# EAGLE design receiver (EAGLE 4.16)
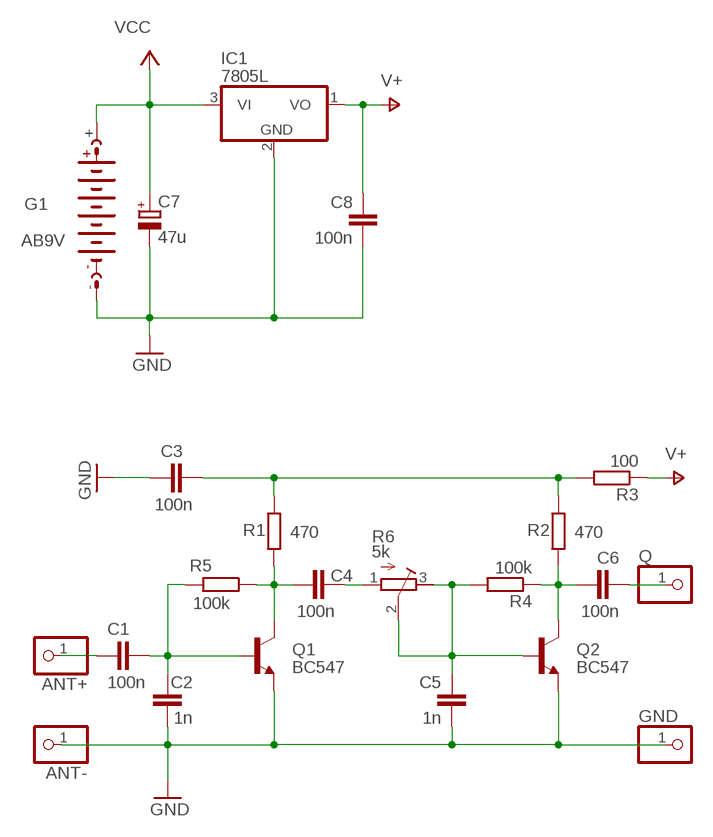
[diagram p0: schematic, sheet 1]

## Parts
ANT+  PINHD-1X1  [1X01]
ANT-  PINHD-1X1  [1X01]
C1  100n  C-EU050-035X075  [C050-035X075]
C2  1n  C-EU050-035X075  [C050-035X075]
C3  100n  C-EU050-035X075  [C050-035X075]
C4  100n  C-EU050-035X075  [C050-035X075]
C5  1n  C-EU050-035X075  [C050-035X075]
C6  100n  C-EU050-035X075  [C050-035X075]
C7  47u  CPOL-EUE5-10.5  [E5-10,5]
C8  100n  C-EU050-035X075  [C050-035X075]
G1  AB9V  [AB9V]
GND  PINHD-1X1  [1X01]
IC1  7805L  [TO92]
Q  PINHD-1X1  [1X01]
Q1  BC547  [TO92]
Q2  BC547  [TO92]
R1  470  R-EU_0411/3V  [0411V]
R2  470  R-EU_0411/3V  [0411V]
R3  100  R-EU_0411/3V  [0411V]
R4  100k  R-EU_0411/3V  [0411V]
R5  100k  R-EU_0411/3V  [0411V]
R6  5k  R-TRIMM3339P  [RTRIM3339P]

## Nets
GND: ANT-.1 C2.1 C3.1 C5.1 C7.- C8.1 G1.- GND.1 IC1.2(GND) Q1.1(E) Q2.1(E)
N$1: C1.1 C2.2 Q1.2(B) R5.2
N$2: C4.2 R6.1(E)
N$3: C4.1 Q1.3(C) R1.1 R5.1
N$4: ANT+.1 C1.2
N$5: C6.1 Q2.3(C) R2.1 R4.1
N$6: C3.2 R1.2 R2.2 R3.2
N$7: C6.2 Q.1
N$12: C5.2 Q2.2(B) R4.2 R6.2(S) R6.3(A)
V+: C8.2 IC1.1(VO) R3.1
VCC: C7.+ G1.+ IC1.3(VI)

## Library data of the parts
ANT+ ANT- GND Q = pinhead:PINHD-1X1: PIN HEADER
C1-C6 C8 = rcl:C-EU: CAPACITOR, European symbol
C7 = rcl:CPOL-EU: POLARIZED CAPACITOR, European symbol
G1 = battery:AB9V: 9-V BATTERY CLIP
IC1 = linear:78*: Positive VOLTAGE REGULATOR Source: http://cache.national.com/ds/LM/LM78L05.pdf http://www.fairchildsemi.com/ds/LM/LM7805.pdf
Q1 Q2 = transistor-npn:BC547*: NPN Transistor
R1-R5 = rcl:R-EU_: RESISTOR, European symbol
R6 = rcl:R-TRIMM: Trimm resistor

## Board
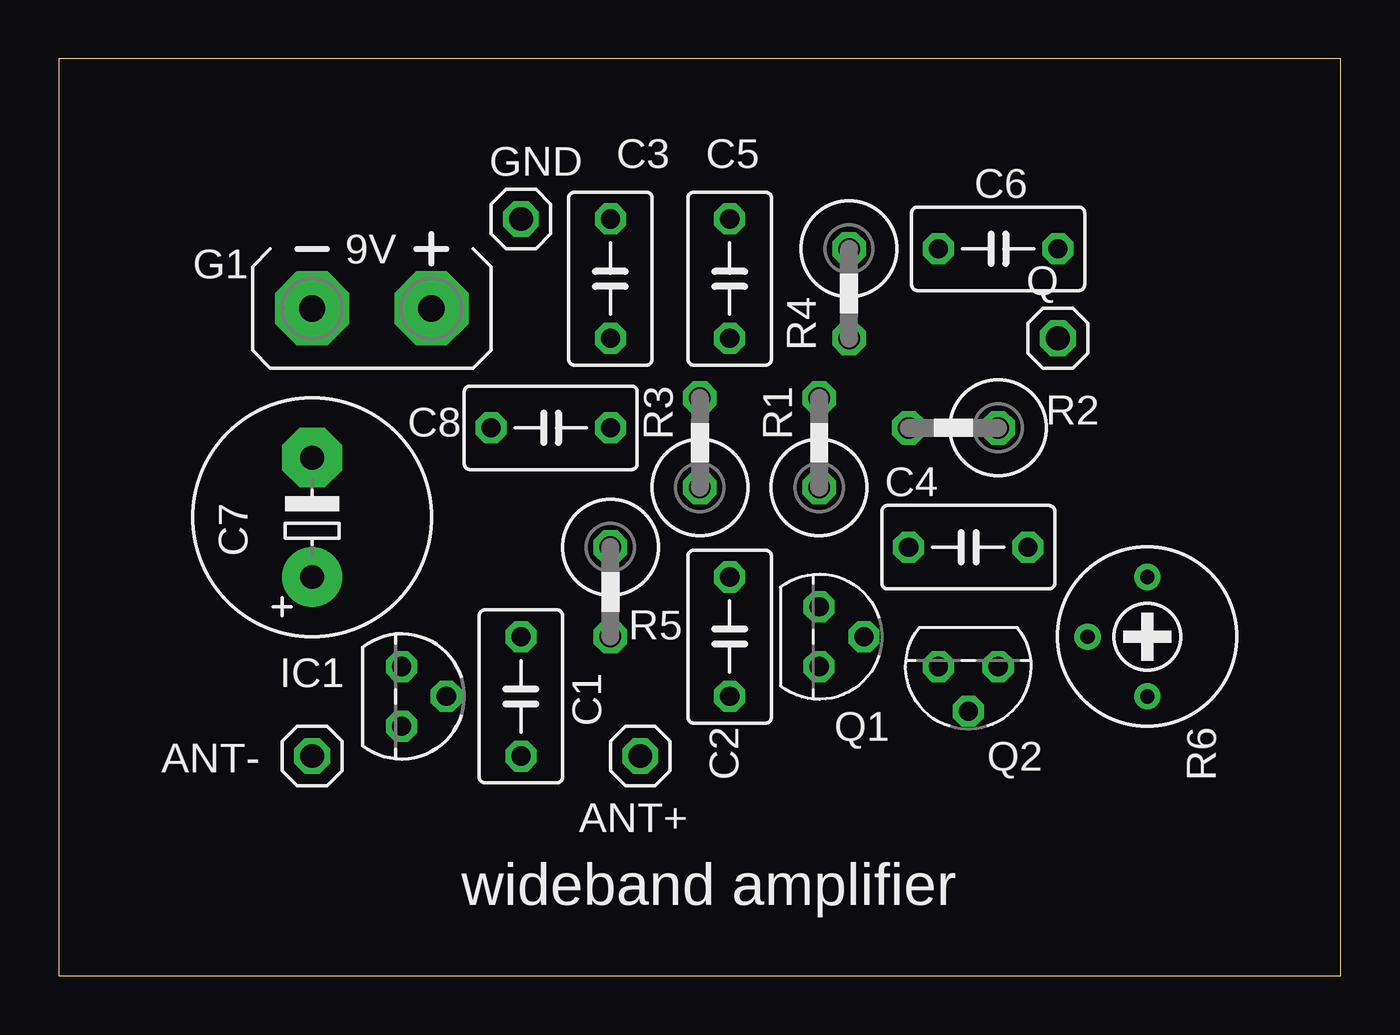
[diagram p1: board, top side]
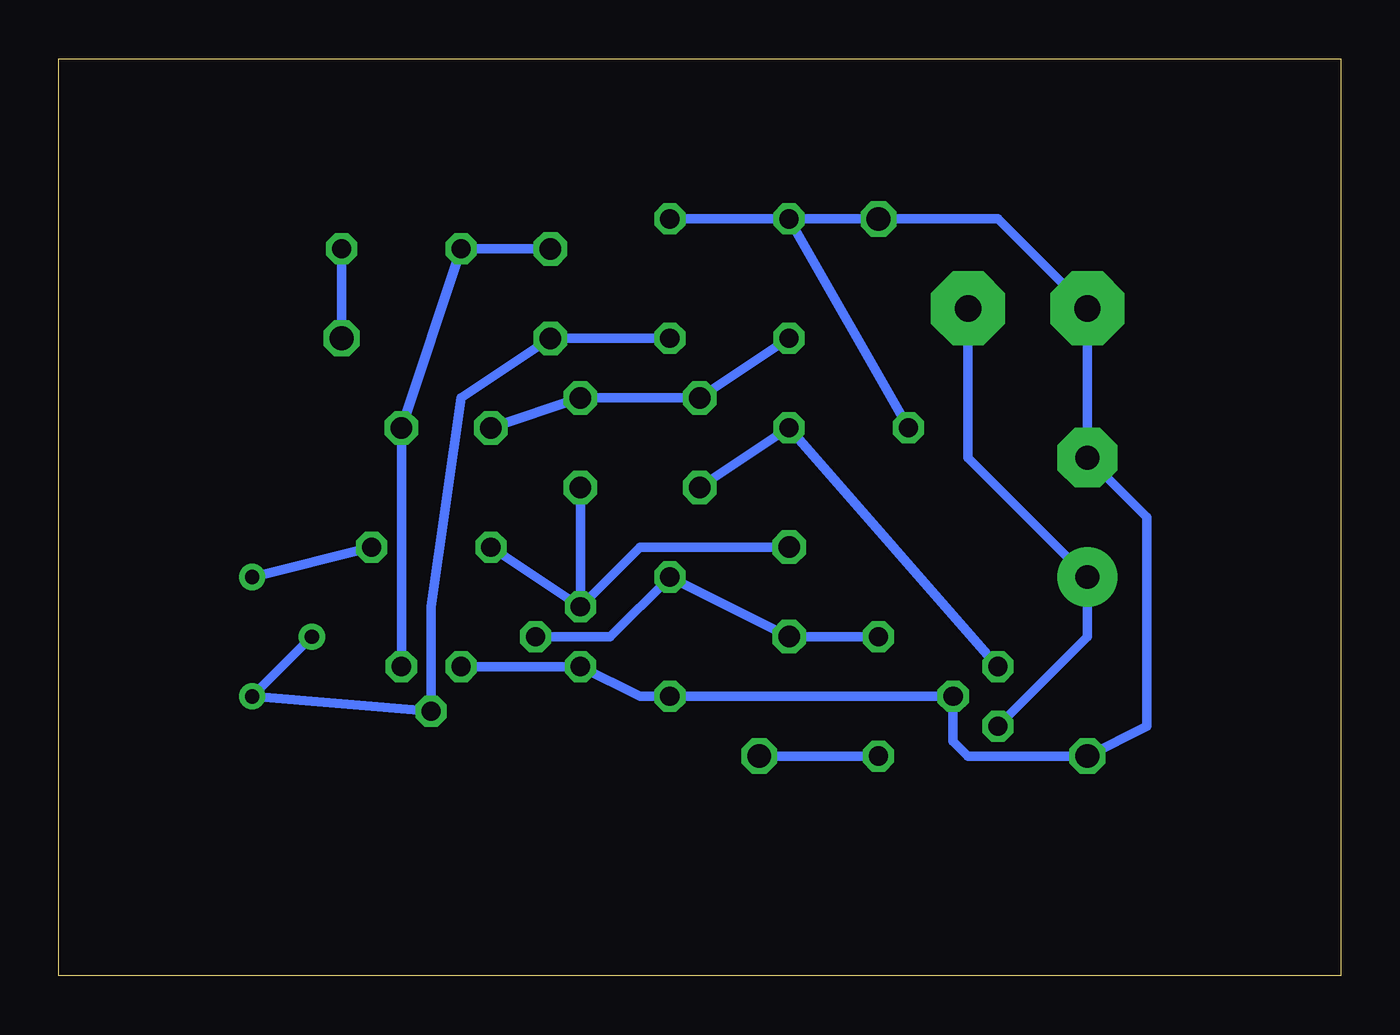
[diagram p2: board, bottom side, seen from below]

Size 54.59 x 39.04 mm. Coordinates in mm from the lower left corner, seen from the top.
Outline: 0,0 54.59,0 54.59,39.04 0,39.04 0,0
Copper layers (1*16): Top 0.035mm / dielectric 1.5mm / Bottom 0.035mm
Design rules "default": minimum track width 10mil, minimum drill 24mil, track to track 8mil, track to pad 8mil, pad to pad 8mil, via to via 8mil, smd to smd 8mil, copper to edge 40mil, drill to drill 8mil, minimum pad ring 10mil, minimum via ring 8mil, stop-mask expansion 4mil, vias tented up to drill 0mil, thermal gap 10mil

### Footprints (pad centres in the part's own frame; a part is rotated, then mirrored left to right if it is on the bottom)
1X01 = drill 1.016 octagon: 1 0,0
C050-035X075 = drill 0.813 octagon: 1 -2.54,0; 2 2.54,0
E5-10,5 = drill 1.016 pad 2.54 round: + -2.54,0 | drill 1.016 pad 2.54 octagon: - 2.54,0
AB9V = drill 1.118 pad 3.15 octagon: + 0,2.54; - 0,-2.54
TO92 = drill 0.813 octagon: 1 -1.27,0; 2 0,1.905; 3 1.27,0
TO92' = drill 0.813 octagon: 1 1.27,0; 2 0,1.905; 3 -1.27,0
0411V = drill 0.914 octagon: 1 -2.54,0; 2 1.27,0
RTRIM3339P = drill 0.61 round: 1 -2.54,0; 2 0,-2.54; 3 2.54,0

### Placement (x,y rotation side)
ANT+  24.76,9.36 0 top
ANT-  10.79,9.36 0 top
C1  19.68,11.9 270 top
C2  28.57,14.44 90 top
C3  23.49,29.68 270 top
C4  38.73,18.25 0 top
C5  28.57,29.68 270 top
C6  40,30.95 0 top
C7  10.79,19.52 90 top
C8  20.95,23.33 0 top
G1  13.33,28.41 270 top
GND  19.68,32.22 0 top
IC1  14.6,11.9 270 top
Q  42.54,27.14 0 top
Q1  BC547  [TO92']  32.38,14.44 270 top
Q2  BC547  [TO92']  38.73,13.17 180 top
R1  32.38,23.33 90 top
R2  37.46,23.33 180 top
R3  27.3,23.33 90 top
R4  33.65,28.41 270 top
R5  23.49,15.71 270 top
R6  46.35,14.44 270 top

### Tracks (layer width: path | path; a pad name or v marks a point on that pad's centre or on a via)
GND
  Bottom 0.406: GND.1 14.6,32.22 G1.- C7.- 8.25,19.52 8.25,10.63 ANT-.1 15.87,9.36 16.5,10 IC1.2 C2.1 29.84,11.9 Q1.1 Q2.1 | GND.1 C3.1 | C3.1 C8.1 | GND.1 C3.1 | C3.1 C5.1
N$1
  Bottom 0.406: C1.1 20.95,14.44 R5.2 C2.2 31.11,14.44 Q1.2
N$2
  Bottom 0.406: C4.2 R6.1
N$3
  Bottom 0.406: R5.1 29.84,18.25 Q1.3 | Q1.3 R1.1 | Q1.3 C4.1
N$4
  Bottom 0.406: C1.2 ANT+.1
N$5
  Bottom 0.406: R4.1 C6.1 R2.1 Q2.3
N$6
  Bottom 0.406: C3.2 R3.2 R1.2 R2.2
N$7
  Bottom 0.406: Q.1 C6.2
N$12
  Bottom 0.406: C5.2 R4.2 37.46,24.6 38.73,15.71 Q2.2 R6.3 R6.2
V+
  Bottom 0.406: IC1.1 C8.2 R3.1
VCC
  Bottom 0.406: G1.+ 15.87,22.06 C7.+ 10.79,14.44 IC1.3

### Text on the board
tPlace: wideband amplifier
